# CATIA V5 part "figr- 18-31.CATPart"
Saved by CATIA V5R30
Part number: Part1
Bounding box of the stored display mesh (mm): x -37.5 to 37.5, y -50 to 50, z 0 to 59.069
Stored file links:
  D:\PROJECTS\CATIA V56R 2020\Resources\Parts File\c18_catia_v6_6r2020_prt\figr- 18-31.CATPart
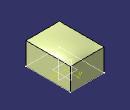
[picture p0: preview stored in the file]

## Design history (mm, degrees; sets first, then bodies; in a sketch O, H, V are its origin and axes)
Set1
  Sketch1 on xy-plane, origin (0, 0, 0), H (1, 0, 0), V (0, 1, 0)
    line L1 (37.5, 50) -> (37.5, -50)
    line L2 (37.5, -50) -> (-37.5, -50)
    line L3 (-37.5, -50) -> (-37.5, 50)
    line L4 (-37.5, 50) -> (37.5, 50)
    length L4 = 75
    length L1 = 100
    vertical: L1 V, L3 V
    horizontal: L2 H, L4 H
    equidistance: L1 L3 O, L2 L4 O
  Extrude1: Element1 Sketch1, Lim1 50, Lim2 0
  DatumSurface1
Body1 (main body)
